(* Logix 5000 project; controller MVI69DFNT vendor 1 type 14 code 65 rev 16.20; software revision 16.04 *)
// MVI69_DFNT

TASK MainTask (continuous, watchdog 500 ms) : MainProgram

MODULES
   Controller : vendor 1 type 14 code 65 (CompactLogixL35Controller 0, rev 16.20)
      LocalENB : 1769-L35E Ethernet Port (CompactLogixL35Ethernet 1, Ethernet 192.168.0.159, rev 16.1)
      Local : CompactBus (CompactVirtualAdapter 3, rev 16.1, Output RPI 2 ms)
         MVI69DFNT : 1769-MODULE (Compact 1, rev 1.1, Output RPI 2 ms)   // MVI69_DFNT
END_MODULES

TYPE DFNT_ClientStatus :   // This object is used to store Client Status.
STRUCT
   CmdReq : INT;   // Total number of command list requests sent
   CmdResp : INT;   // Total number of command list responses received
   CmdErr : INT;   // Total number of command list errors
   Requests : INT;   // Total number of requests for port
   Responses : INT;   // Total number of responses for port
   ErrSent : INT;   // Total number of errors sent
   ErrRec : INT;   // Total number of errors received
   CfgErrWord : INT;   // Configuration Error Word
   CurErr : INT;   // Current Error code
   LastErr : INT;   // Last recorded error code
END_STRUCT
END_TYPE

TYPE DFNTBlock :   // This object is used to store the block transfer statistics for the MVI69-DFNT module.
STRUCT
   Read : INT;   // Total number of read block transfers
   Write : INT;   // Total number of write block transfers
   Parse : INT;   // Total number of blocks parsed
   Event : INT;   // Total number of event blocks received
   Cmd : INT;   // Total number of command blocks received
   Err : INT;   // Total number of block transfer errors
END_STRUCT
END_TYPE

TYPE DFNTCommandsStatus :   // DFNT CommandsStatus
STRUCT
   CommandStartIndex : INT;   // Index of first command
   CommandCount : INT;   // Number of commands (1 to 50)
   CMDErrorStat : INT[50];   // Array of command error codes
END_STRUCT
END_TYPE

TYPE DFNTCONFIG :   // MVI69-MCM block transfer size configuration.
STRUCT
   BlockTransferSize : INT;   // This value should be 60, 120 or 240 words. Needs to match Module's backplane Connection Parameters.
END_STRUCT
END_TYPE

TYPE DFNTConnectionInput :   // Connection pin for the Add-On instruction.
STRUCT
   Data : INT[62];   // Add-On data array for connection input pin.
END_STRUCT
END_TYPE

TYPE DFNTConnectionOutput :   // Connection pin for the Add-On instruction.
STRUCT
   Data : INT[61];   // Add-On data array for connection output pin.
END_STRUCT
END_TYPE

TYPE DFNTCONTROL :   // MVI69-DFNT module control
STRUCT
   BootTimer : TIMER;   // Timer to reset reboot request
   WarmBoot : BOOL;   // Warm Boot
   ColdBoot : BOOL;   // Cold Boot
   ControlBits : DFNTControlBits;   // ControlBits for special command requests
END_STRUCT
END_TYPE

TYPE DFNTControlBits :   // DFNT ControlBits
STRUCT
   EnableCommands : BOOL;   // Dynamically enables configured commands (enable code = 1)
   DisableCommands : BOOL;   // Dynamically disables configured commands (enable code = 0)
   ConditionalCommands : BOOL;   // Dynamically sets configured commands as conditional (enable code = 2)
   GetServersStat : DFNTServerStatusBits;   // Retrieves server status
   GetModuleStat : BOOL;   // Retrieves module status
   StatusCommandErr : BOOL;   // Retrieves command errors
END_STRUCT
END_TYPE

TYPE DFNTDATA :
STRUCT
   ReadData : INT[600];   // Data read from the module to the processor
   WriteData : INT[600];   // Data written from the processor to the module
END_STRUCT
END_TYPE

TYPE DFNTModuleDef :   // DFNT ModuleDef
STRUCT
   CONFIG : DFNTCONFIG;   // Configuration information
   DATA : DFNTDATA;   // DFNT data transferred between module and processor
   STATUS : DFNTSTATUS;   // Status information in each read block
   CONTROL : DFNTCONTROL;   // Optional requests from the processor to the module
   UTIL : DFNTUTIL;   // Used only internally for ladder processing
END_STRUCT
END_TYPE

TYPE DFNTPort80Status :   // DFNT Port 80 Status
STRUCT
   No_of_Requests : INT;   // Total Number of HTTP requests for the module
   No_of_Responses : INT;   // Total Number of HTTP response Messages generated
END_STRUCT
END_TYPE

TYPE DFNTServerStatus :   // DFNT Server Status
STRUCT
   SocketState : INT;   // DFNT Server Status
   ConnectionState : INT;   // Connection state
   OpenCount : INT;   // Total number of times the server has performed an open operation.
   EstablishCount : INT;   // Total number of times a connection has been established on the server.
   CloseCount : INT;   // Total number of times the server has performed a close operation.
   ReadCount : INT;   // Total number of packets received by the server.
   MessageCount : INT;   // Total number of message receive by the server.
   WriteCount : INT;   // Total number of packets sent from the server to the client.
   Timeout : INT;   // Total number of times the server as reached a connection timeout condition.
   HostPort : INT;   // Service port on client connected to the server.
   HostIPAddr : INT[2];   // IP address of the client connected to the server.
END_STRUCT
END_TYPE

TYPE DFNTServerStatusBits :   // Control Bits to poll Server status information
STRUCT
   GetServersStat_0_4 : BOOL;   // Server Status Data of Slaves 0 to 4
   GetServersStat_5_9 : BOOL;   // Server Status Data of Slaves 5 to 9
   GetServersStat_10_14 : BOOL;   // Server Status Data of Slaves 10 to 14
   GetServersStat_15_19 : BOOL;   // Server Status Data of Slaves 15 to 19
END_STRUCT
END_TYPE

TYPE DFNTSTATUS :   // This status data is returned on each read block and can be used to detect proper module operation.
STRUCT
   PassCnt : INT;   // Program cycle counter
   Product : INT[2];   // Product number
   Rev : INT[2];   // Firmware Revision
   OP : INT[2];   // Operating System revision
   Run : INT[2];   // Run number
   Block : DFNTBlock;   // Block transfer statistics
   Port80Stats : DFNTPort80Status;   // Status of port 80
   ClientStatus : DFNT_ClientStatus;   // Client status data
   DFNTServer : DFNTServerStatus[20];   // MNet server status data
   CommandStatus : DFNTCommandsStatus;   // DFNT Command Status
END_STRUCT
END_TYPE

TYPE DFNTUTIL :   // Internal ladder usage - should not be accessed by user application
STRUCT
   ReadDataSizeGet : INT;   // Gets ReadData Array Length.
   WriteDataSizeGet : INT;   // Gets WriteData Array Length.
   ReadDataBlkCount : INT;   // holds the value of the Block Counts of the Read Data Array.
   WriteDataBlkCount : INT;   // holds the value of the Block Counts of the Write Data Array.
   RBTSremainder : INT;   // The remainder of the 60, 120 or 240 block to transfer.
   WBTSremainder : INT;   // The remainder of the 60, 120 or 240 block to transfer.
   LastRead : INT;   // Backplane last read
   LastWrite : INT;   // Backplane last write
   BlockIndex : INT;   // Block index
END_STRUCT
END_TYPE

ADD_ON_INSTRUCTION AOI69DFNT   (* revision 1.4 *)
// Add-On for the MVI69-DFNT module.
// Revision note:
// v1.2 - re-exported AOI rung
// v1.3 - Fix to ServerStatus Functionality
// v1.4 - Fixed Boot Loop issue found when rebooting
VAR_IN_OUT
   Connection_Input : DFNTConnectionInput; {required}
   Connection_Output : DFNTConnectionOutput; {required}
   DFNT : DFNTModuleDef; {required}
END_VAR

ROUTINE Logic   (* ladder *)
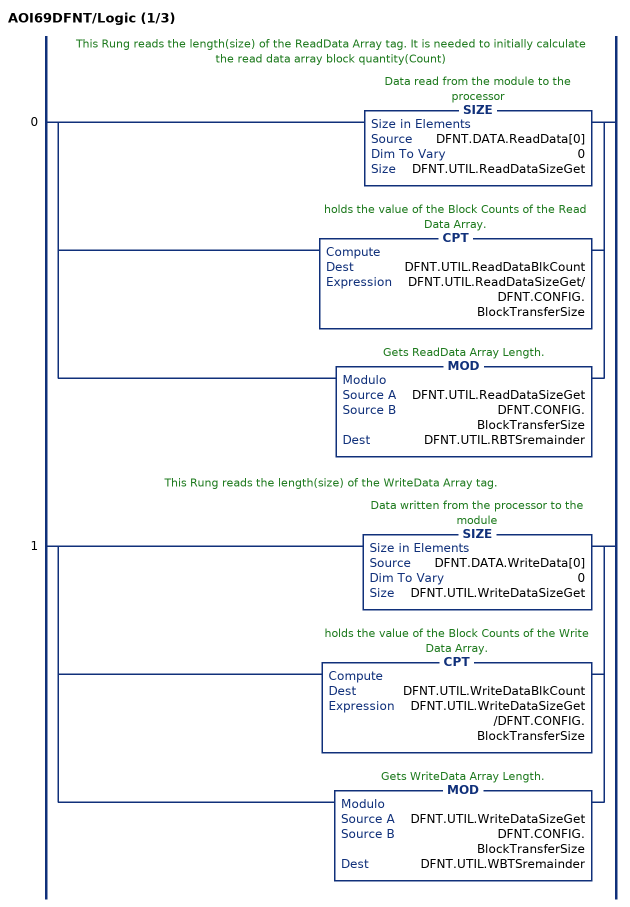
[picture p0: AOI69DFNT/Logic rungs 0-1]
   // This Rung reads the length(size) of the ReadData Array tag. It is needed to initially calculate the read data array block quantity(Count)
   0: [SIZE(DFNT.DATA.ReadData[0],0,DFNT.UTIL.ReadDataSizeGet) ,CPT(DFNT.UTIL.ReadDataBlkCount,DFNT.UTIL.ReadDataSizeGet/DFNT.CONFIG.BlockTransferSize) ,MOD(DFNT.UTIL.ReadDataSizeGet,DFNT.CONFIG.BlockTransferSize,DFNT.UTIL.RBTSremainder) ];
   // This Rung reads the length(size) of the WriteData Array tag.
   1: [SIZE(DFNT.DATA.WriteData[0],0,DFNT.UTIL.WriteDataSizeGet) ,CPT(DFNT.UTIL.WriteDataBlkCount,DFNT.UTIL.WriteDataSizeGet /DFNT.CONFIG.BlockTransferSize) ,MOD(DFNT.UTIL.WriteDataSizeGet,DFNT.CONFIG.BlockTransferSize,DFNT.UTIL.WBTSremainder) ];
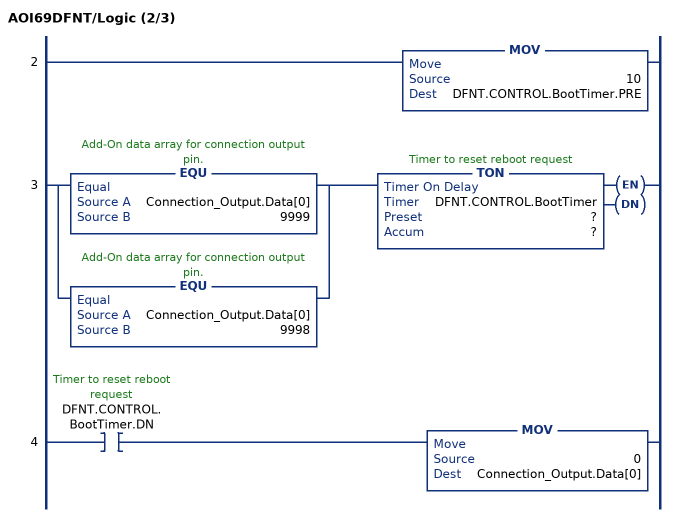
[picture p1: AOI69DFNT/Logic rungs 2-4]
   2: MOV(10,DFNT.CONTROL.BootTimer.PRE);
   3: [EQU(Connection_Output.Data[0],9999) ,EQU(Connection_Output.Data[0],9998) ]TON(DFNT.CONTROL.BootTimer,?,?);
   4: XIC(DFNT.CONTROL.BootTimer.DN)MOV(0,Connection_Output.Data[0]);
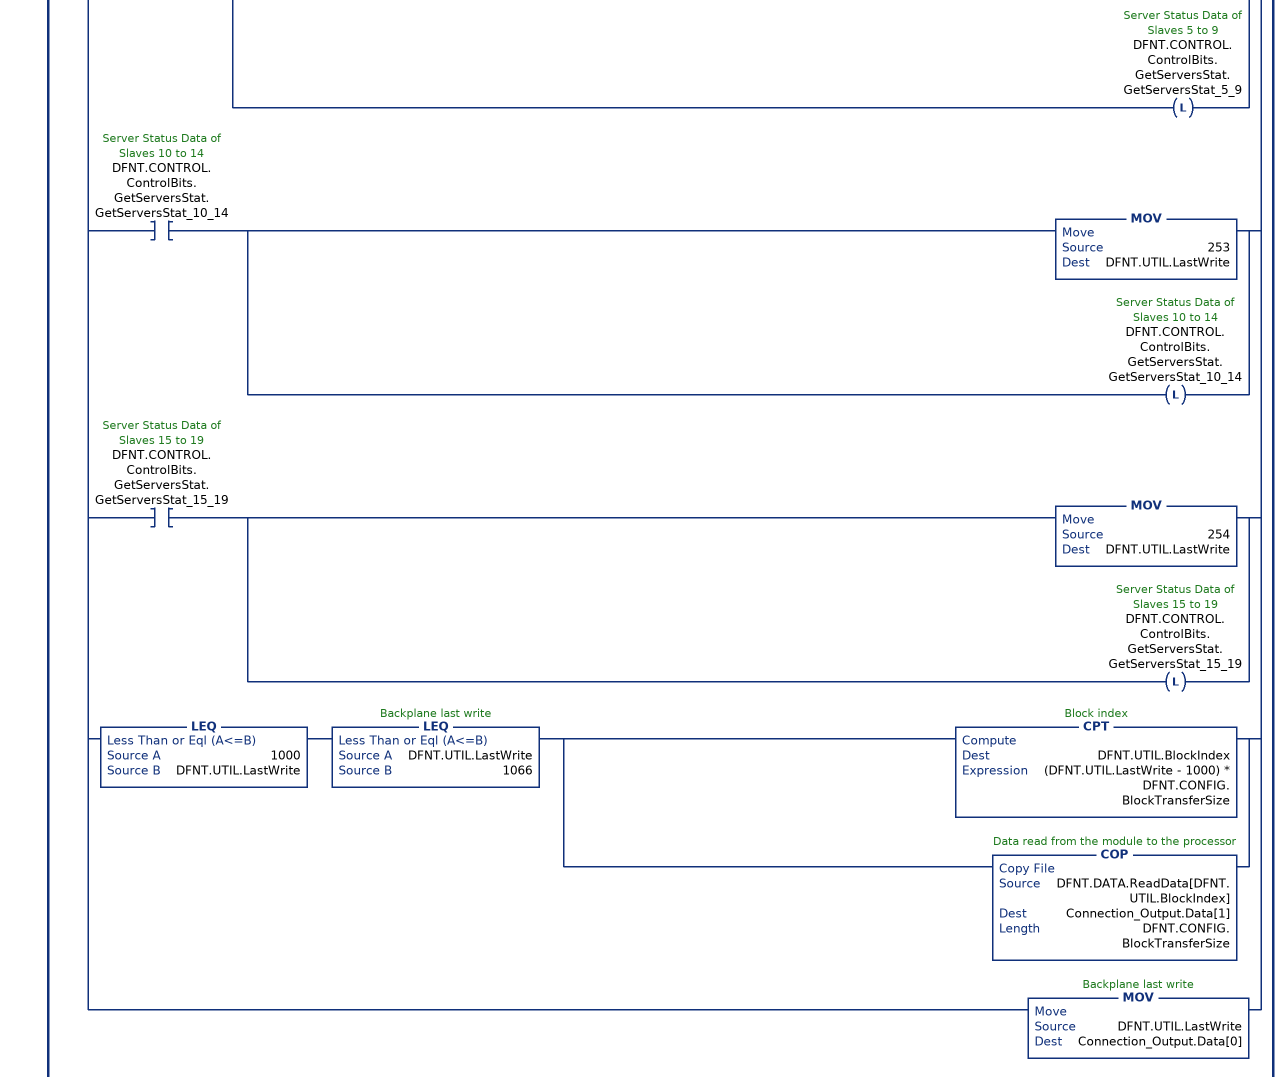
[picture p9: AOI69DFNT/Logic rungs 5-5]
   // The routines will only be scanned once the processor receives a new read block ID from the module
   5: NEQ(DFNT.UTIL.LastRead,Connection_Input.Data[0])[MOV(Connection_Input.Data[0],DFNT.UTIL.LastRead) ,GEQ(DFNT.UTIL.LastRead,1) [LEQ(DFNT.UTIL.LastRead,DFNT.UTIL.ReadDataBlkCount) [CPT(DFNT.UTIL.BlockIndex,(DFNT.UTIL.LastRead - 1) * DFNT.CONFIG.BlockTransferSize) ,COP(Connection_Input.Data[2],DFNT.DATA.ReadData[DFNT.UTIL.BlockIndex],DFNT.CONFIG.BlockTransferSize) ] ,CMP(DFNT.UTIL.LastRead - DFNT.UTIL.ReadDataBlkCount = 1) GRT(DFNT.UTIL.RBTSremainder,0) [CPT(DFNT.UTIL.BlockIndex,(DFNT.UTIL.LastRead - 1) * DFNT.CONFIG.BlockTransferSize) ,COP(Connection_Input.Data[2],DFNT.DATA.ReadData[DFNT.UTIL.BlockIndex],DFNT.UTIL.RBTSremainder) ] ] ,[EQU(DFNT.UTIL.LastRead,-1) ,EQU(DFNT.UTIL.LastRead,0) ,EQU(DFNT.UTIL.LastRead,250) ] [COP(Connection_Input.Data[2],DFNT.STATUS.PassCnt,1) ,COP(Connection_Input.Data[3],DFNT.STATUS.Product[0],2) ,COP(Connection_Input.Data[5],DFNT.STATUS.Rev[0],2) ,COP(Connection_Input.Data[7],DFNT.STATUS.OP[0],2) ,COP(Connection_Input.Data[9],DFNT.STATUS.Run[0],2) ,COP(Connection_Input.Data[31],DFNT.STATUS.Block.Read,6) ,COP(Connection_Input.Data[14],DFNT.STATUS.Port80Stats.No_of_Requests,2) ,COP(Connection_Input.Data[21],DFNT.STATUS.ClientStatus.CmdReq,10) ] ,EQU(DFNT.UTIL.LastRead,2000) [COP(Connection_Input.Data[2],DFNT.STATUS.CommandStatus.CMDErrorStat[0],50) ,OTU(DFNT.CONTROL.ControlBits.StatusCommandErr) ] ,EQU(DFNT.UTIL.LastRead,251) [COP(Connection_Input.Data[2],DFNT.STATUS.DFNTServer[0].SocketState,60) ,OTU(DFNT.CONTROL.ControlBits.GetServersStat.GetServersStat_0_4) ] ,EQU(DFNT.UTIL.LastRead,252) [COP(Connection_Input.Data[2],DFNT.STATUS.DFNTServer[5].SocketState,60) ,OTU(DFNT.CONTROL.ControlBits.GetServersStat.GetServersStat_5_9) ] ,EQU(DFNT.UTIL.LastRead,253) [COP(Connection_Input.Data[2],DFNT.STATUS.DFNTServer[10].SocketState,60) ,OTU(DFNT.CONTROL.ControlBits.GetServersStat.GetServersStat_10_14) ] ,EQU(DFNT.UTIL.LastRead,254) [COP(Connection_Input.Data[2],DFNT.STATUS.DFNTServer[15].SocketState,60) ,OTU(DFNT.CONTROL.ControlBits.GetServersStat.GetServersStat_15_19) ] ,MOV(Connection_Input.Data[1],DFNT.UTIL.LastWrite) ,XIC(DFNT.CONTROL.ColdBoot) NEQ(DFNT.UTIL.LastRead,0) [MOV(9999,DFNT.UTIL.LastWrite) ,OTU(DFNT.CONTROL.ColdBoot) ] ,XIC(DFNT.CONTROL.WarmBoot) NEQ(DFNT.UTIL.LastRead,0) [MOV(9998,DFNT.UTIL.LastWrite) ,OTU(DFNT.CONTROL.WarmBoot) ] ,GEQ(DFNT.UTIL.LastWrite,1) [LEQ(DFNT.UTIL.LastWrite,DFNT.UTIL.WriteDataBlkCount) [CPT(DFNT.UTIL.BlockIndex,(DFNT.UTIL.LastWrite - 1) * DFNT.CONFIG.BlockTransferSize) ,COP(DFNT.DATA.WriteData[DFNT.UTIL.BlockIndex],Connection_Output.Data[1],DFNT.CONFIG.BlockTransferSize) ] ,CMP(DFNT.UTIL.LastWrite - DFNT.UTIL.WriteDataBlkCount = 1) GRT(DFNT.UTIL.WBTSremainder,0) [CPT(DFNT.UTIL.BlockIndex,(DFNT.UTIL.LastWrite - 1) * DFNT.CONFIG.BlockTransferSize) ,COP(DFNT.DATA.WriteData[DFNT.UTIL.BlockIndex],Connection_Output.Data[1],DFNT.UTIL.WBTSremainder) ] ] ,XIC(DFNT.CONTROL.ControlBits.StatusCommandErr) [MOV(2000,DFNT.UTIL.LastWrite) ,MOV(DFNT.STATUS.CommandStatus.CommandStartIndex,Connection_Output.Data[1]) ,MOV(DFNT.STATUS.CommandStatus.CommandCount,Connection_Output.Data[2]) ,OTL(DFNT.CONTROL.ControlBits.StatusCommandErr) ] ,XIC(DFNT.CONTROL.ControlBits.DisableCommands) [MOV(DFNT.STATUS.CommandStatus.CommandCount,Connection_Output.Data[1]) ,MOV(DFNT.STATUS.CommandStatus.CommandStartIndex,Connection_Output.Data[2]) ,MOV(3000,DFNT.UTIL.LastWrite) ,OTU(DFNT.CONTROL.ControlBits.DisableCommands) ] ,XIC(DFNT.CONTROL.ControlBits.EnableCommands) [MOV(DFNT.STATUS.CommandStatus.CommandCount,Connection_Output.Data[1]) ,MOV(DFNT.STATUS.CommandStatus.CommandStartIndex,Connection_Output.Data[2]) ,MOV(3001,DFNT.UTIL.LastWrite) ,OTU(DFNT.CONTROL.ControlBits.EnableCommands) ] ,XIC(DFNT.CONTROL.ControlBits.ConditionalCommands) [MOV(DFNT.STATUS.CommandStatus.CommandCount,Connection_Output.Data[1]) ,MOV(DFNT.STATUS.CommandStatus.CommandStartIndex,Connection_Output.Data[2]) ,MOV(3002,DFNT.UTIL.LastWrite) ,OTU(DFNT.CONTROL.ControlBits.ConditionalCommands) ] ,XIC(DFNT.CONTROL.ControlBits.GetModuleStat) [MOV(250,DFNT.UTIL.LastWrite) ,OTU(DFNT.CONTROL.ControlBits.GetModuleStat) ] ,XIC(DFNT.CONTROL.ControlBits.GetServersStat.GetServersStat_0_4) [MOV(251,DFNT.UTIL.LastWrite) ,OTL(DFNT.CONTROL.ControlBits.GetServersStat.GetServersStat_0_4) ] ,XIC(DFNT.CONTROL.ControlBits.GetServersStat.GetServersStat_5_9) [MOV(252,DFNT.UTIL.LastWrite) ,OTL(DFNT.CONTROL.ControlBits.GetServersStat.GetServersStat_5_9) ] ,XIC(DFNT.CONTROL.ControlBits.GetServersStat.GetServersStat_10_14) [MOV(253,DFNT.UTIL.LastWrite) ,OTL(DFNT.CONTROL.ControlBits.GetServersStat.GetServersStat_10_14) ] ,XIC(DFNT.CONTROL.ControlBits.GetServersStat.GetServersStat_15_19) [MOV(254,DFNT.UTIL.LastWrite) ,OTL(DFNT.CONTROL.ControlBits.GetServersStat.GetServersStat_15_19) ] ,LEQ(1000,DFNT.UTIL.LastWrite) LEQ(DFNT.UTIL.LastWrite,1066) [CPT(DFNT.UTIL.BlockIndex,(DFNT.UTIL.LastWrite - 1000) * DFNT.CONFIG.BlockTransferSize) ,COP(DFNT.DATA.ReadData[DFNT.UTIL.BlockIndex],Connection_Output.Data[1],DFNT.CONFIG.BlockTransferSize) ] ,MOV(DFNT.UTIL.LastWrite,Connection_Output.Data[0]) ];
END_ROUTINE
END_ADD_ON_INSTRUCTION

VAR_GLOBAL   (* controller tags *)
   AOI69DFNT : AOI69DFNT;
   Connection_Input : DFNTConnectionInput := (Data[1] := 6, Data[2] := -26938, Data[3] := 17988, Data[4] := 13902, Data[5] := 11825, Data[6] := 12338, Data[7] := 14128, Data[8] := 13616, Data[9] := 12594, Data[10] := 12592, Data[21] := 3220, Data[23] := 3235, Data[24] := 9660, Data[25] := 6440, Data[29] := -4090, Data[30] := -4090, Data[31] := 14107, Data[32] := 14108, Data[33] := 14108);
   Connection_Output : DFNTConnectionOutput := (Data[0] := 3);
   DFNT : DFNTModuleDef;
   MJFAULTS : DINT[12] := ([0] := -1848259544, [1] := 222672, [3] := -1884573261, [4] := 222672);
END_VAR

PROGRAM MainProgram   (* main routine MainRoutine *)
VAR
   Ipaddress : BOOL;   // Set IP Address
   MCM : DINT;
END_VAR

ROUTINE MainRoutine   (* ladder *)
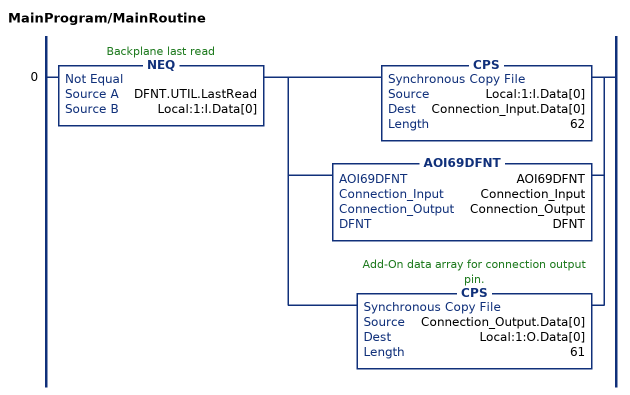
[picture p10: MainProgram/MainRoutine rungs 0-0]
   0: NEQ(DFNT.UTIL.LastRead,Local:1:I.Data[0])[CPS(Local:1:I.Data[0],Connection_Input.Data[0],62) ,AOI69DFNT(AOI69DFNT,Connection_Input,Connection_Output,DFNT) ,CPS(Connection_Output.Data[0],Local:1:O.Data[0],61) ];
END_ROUTINE
END_PROGRAM

PROGRAM powerup   (* main routine powerup *)

ROUTINE powerup   (* ladder *)
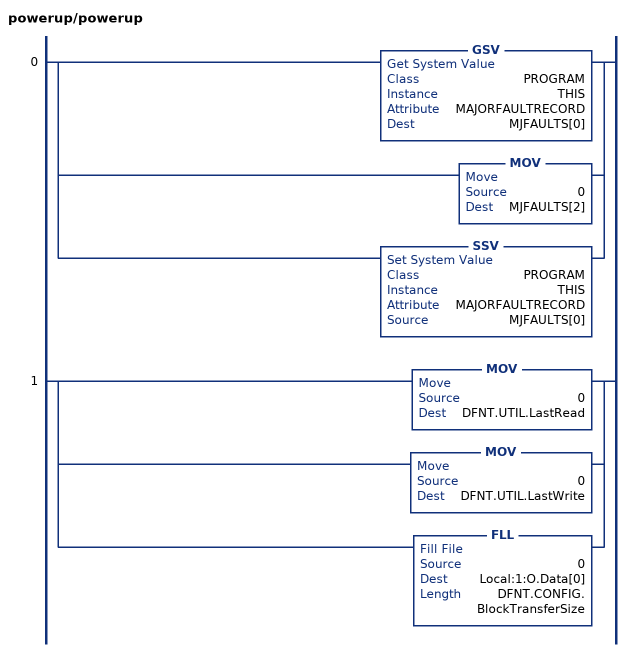
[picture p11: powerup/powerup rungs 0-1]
   0: [GSV(PROGRAM,THIS,MAJORFAULTRECORD,MJFAULTS[0]) ,MOV(0,MJFAULTS[2]) ,SSV(PROGRAM,THIS,MAJORFAULTRECORD,MJFAULTS[0]) ];
   1: [MOV(0,DFNT.UTIL.LastRead) ,MOV(0,DFNT.UTIL.LastWrite) ,FLL(0,Local:1:O.Data[0],DFNT.CONFIG.BlockTransferSize) ];
END_ROUTINE
END_PROGRAM
